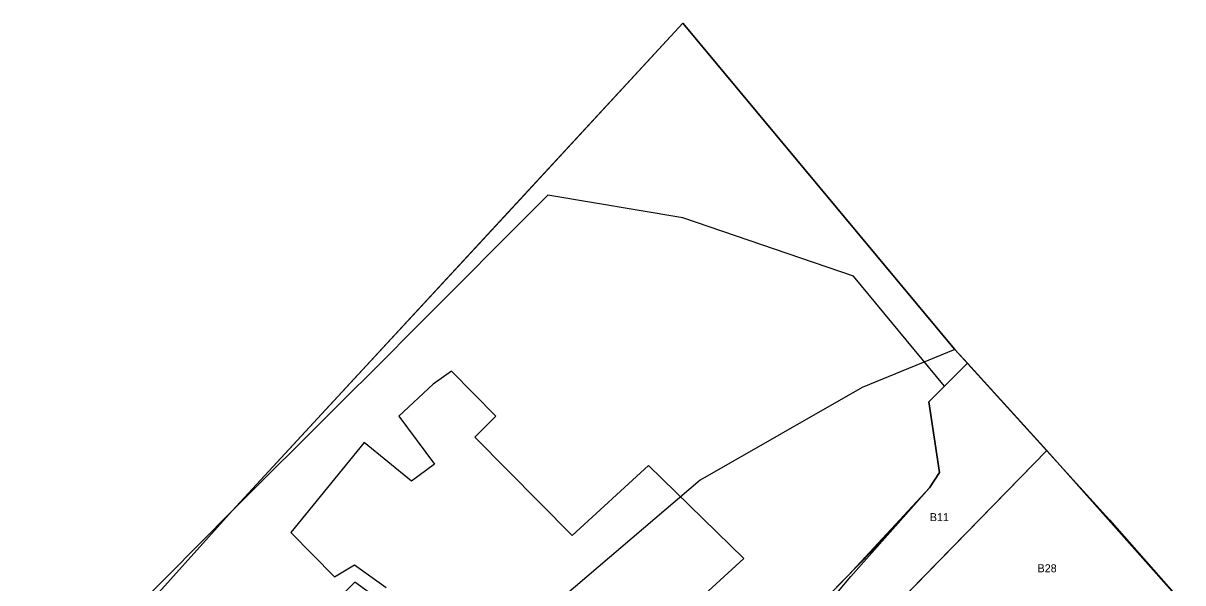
# Model space of a CAD drawing. Extents: x 2253035 to 2279930, y 13774972 to 13793443.
# Drawn here: x 2255344 to 2256503, y 13792138 to 13792697 of the extents above; entities that cross this region are included whole.
import ezdxf

# ---------------------------------------------------------------- set-up
doc = ezdxf.new("R2010")
doc.units = 0
for name, color, linetype in [('E_Utility_ATT_Fiber', 7, 'Continuous'), ('E_Utility_Gas_Gas Line_GL_Elevation', 7, 'Continuous'), ('E_Utility_Water_Valve Cover Water_VCW_point', 7, 'Continuous'), ('E_Utility_Water_Water Line_WL_Description', 7, 'Continuous'), ('E_Utility_Water_Water Line_WL_Elevation', 7, 'Continuous'), ('E_Utility_Water_Water Valve_WV_Elevation', 7, 'Continuous')]:
    doc.layers.add(name, color=color, linetype=linetype)

msp = doc.modelspace()

# ---------------------------------------------------------------- linework, layer by layer
at = {"layer": 'E_Utility_ATT_Fiber'}
for p, q in [((2255868.2, 13792525.3), (2255733.1, 13792389.9)), ((2256003, 13792502.5), (2255868.2, 13792525.3)), ((2256173.6, 13792444.4), (2256003, 13792502.5)), ((2256264.6, 13792334.3), (2256173.6, 13792444.4)), ((2255733.1, 13792389.9), (2255703.4, 13792360.1)), ((2255703.4, 13792360.1), (2255656.6, 13792313.2)), ((2256249, 13792318.6), (2256264.6, 13792334.3)), ((2255656.6, 13792313.2), (2255552.7, 13792209.6)), ((2256259.5, 13792247.9), (2256249, 13792318.6)), ((2256249.7, 13792232.7), (2256259.5, 13792247.9)), ((2256168.3, 13792145.2), (2256249.7, 13792232.7)), ((2255552.7, 13792209.6), (2255348.7, 13792004.6)), ((2256116.8, 13792092.4), (2256168.3, 13792145.2))]:
    msp.add_line(p, q, dxfattribs=at)
for points in [[(2256149.4, 13792125.8), (2256131, 13792106.9), (2256116.4, 13792070.8), (2256156.4, 13792054.2), (2256366.8, 13792269.9), (2256287.4, 13792357.2), (2256249, 13792318.6), (2256259.5, 13792247.9), (2256249.7, 13792232.7), (2256192.8, 13792170.3), (2256178.8, 13792155.9)], [(2256366.8, 13792269.9), (2256494.9, 13792126.2), (2256473.8, 13792106.3), (2256237.5, 13792085.4), (2256230.6, 13792130.3)]]:
    msp.add_lwpolyline(points, close=True, dxfattribs=at)
at = {"layer": 'E_Utility_Water_Valve Cover Water_VCW_point'}
msp.add_line((2256274.9, 13792371), (2256182.4, 13792333), dxfattribs=at)
msp.add_lwpolyline([(2256182.4, 13792333), (2256020.2, 13792240.5), (2255705.5, 13791971.9), (2255638.6, 13791873.2), (2255619.9, 13791836.7), (2255688.6, 13791652.4)], dxfattribs=at)
at = {"layer": 'E_Utility_Water_Water Line_WL_Description'}
for points in [[(2255961, 13792067.6), (2256064, 13792161.9), (2255968.8, 13792255.2), (2255892.3, 13792184.9), (2255795, 13792283.4), (2255816.1, 13792304.3), (2255771.8, 13792349.2), (2255753.3, 13792336.4), (2255719.3, 13792304.3), (2255754.7, 13792256.5), (2255731.7, 13792239.5), (2255684.4, 13792278), (2255611.1, 13792188), (2255654.8, 13792143.6), (2255674.9, 13792155.6), (2255706.4, 13792133.1)], [(2255698.3, 13792121.8), (2255675.1, 13792138.4), (2255650.5, 13792114)]]:
    msp.add_lwpolyline(points, dxfattribs=at)
at = {"layer": 'E_Utility_Water_Water Line_WL_Elevation'}
msp.add_lwpolyline([(2256121.5, 13792085.4), (2256170.8, 13792144.2), (2256249.7, 13792232.7), (2256259.5, 13792247.9), (2256249, 13792318.6), (2256287.4, 13792357.2), (2256274.9, 13792371), (2256003, 13792697.3), (2255828, 13792507.7), (2255687.3, 13792355.3), (2255552.7, 13792209.6), (2255414.6, 13792056)], dxfattribs=at)
at = {"layer": 'E_Utility_Water_Water Valve_WV_Elevation'}
msp.add_lwpolyline([(2255391, 13791330.1), (2255459.8, 13791397.2), (2255383.3, 13791459.9), (2255493.6, 13791567.1), (2255547.3, 13791645.6), (2255606, 13791701.9), (2255343.7, 13791984.8), (2255414.6, 13792056), (2255552.7, 13792209.6), (2256003, 13792697.3), (2256274.9, 13792371), (2256429.6, 13792200.7), (2256502.7, 13792117.4), (2256310.1, 13791948.1), (2256237.1, 13792031.8), (2256159.7, 13792002), (2256121.5, 13791961), (2255952.3, 13791795.3), (2255623, 13791457.5), (2255517, 13791344.4)], dxfattribs=at)

# ---------------------------------------------------------------- texts
at = {"layer": 'E_Utility_Gas_Gas Line_GL_Elevation'}
for s, p in [('B11', (2256249.9, 13792199.4)), ('B28', (2256357.6, 13792148.3))]:
    msp.add_text(s, height=8, dxfattribs=at).set_placement(p)

doc.saveas('drawing.dxf')
